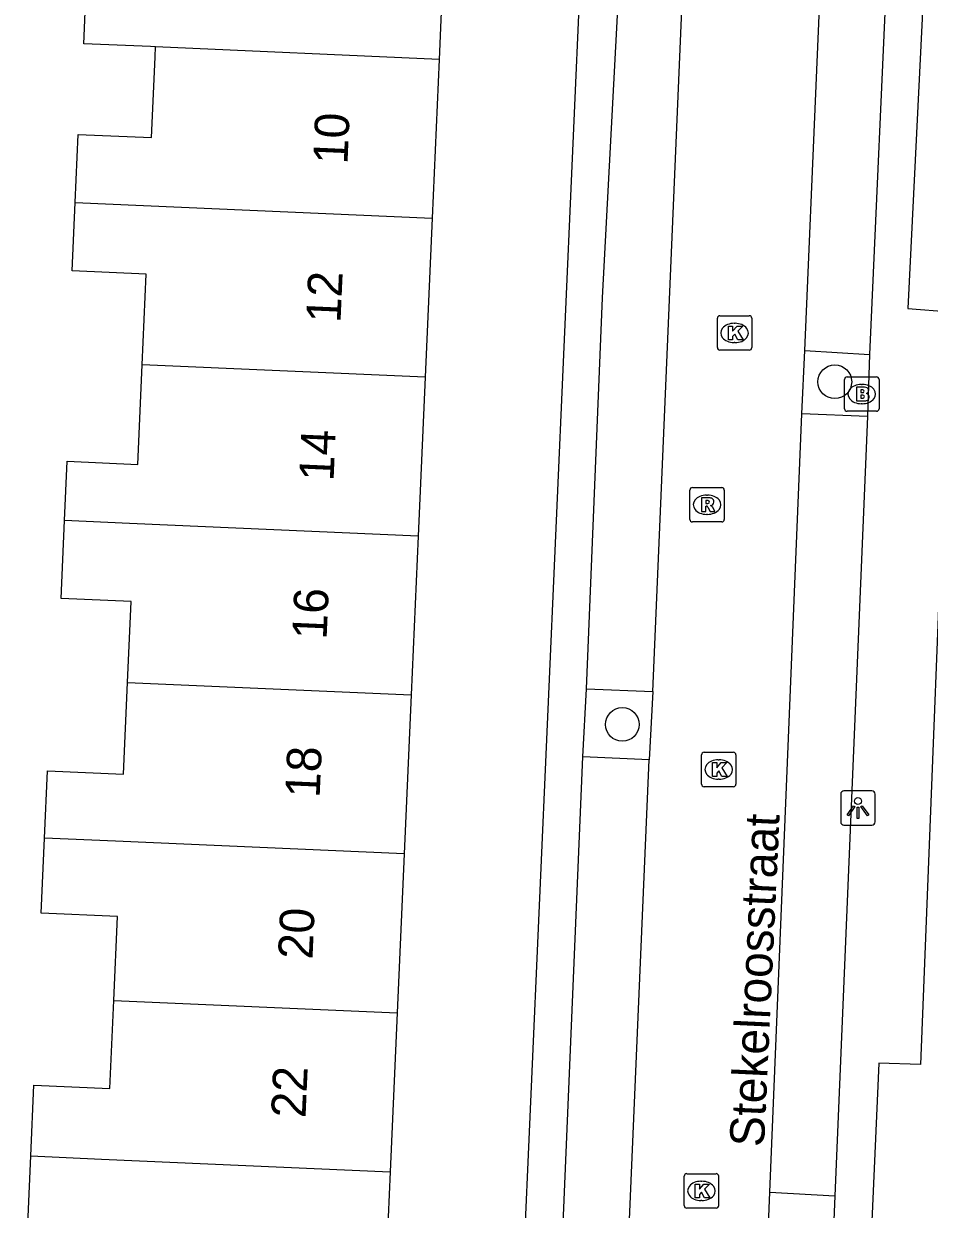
# Model space of a CAD drawing. Extents: x 162250 to 162654, y 380744 to 381605.
# Drawn here: x 162324.04 to 162350.32, y 381047.28 to 381081.68 of the extents above; entities that cross this region are included whole.
import ezdxf

# ---------------------------------------------------------------- set-up
doc = ezdxf.new("R2010")
doc.units = 0
for name, color, linetype in [('IMGEO_Boom', 7, 'Continuous'), ('IMGEO_Brandkraan', 7, 'Continuous'), ('IMGEO_Kolk', 7, 'Continuous'), ('IMGEO_Lichtpunt', 7, 'Continuous'), ('IMGEO_Openbare_ruimte_label', 7, 'Continuous'), ('IMGEO_Pand', 7, 'Continuous'), ('IMGEO_Pand_nummerreeks', 7, 'Continuous'), ('IMGEO_Parkeervlak_open', 7, 'Continuous'), ('IMGEO_Rijbaan_lokaal_open', 7, 'Continuous'), ('IMGEO_Rioolput', 7, 'Continuous'), ('IMGEO_Voetpad_open', 7, 'Continuous')]:
    doc.layers.add(name, color=color, linetype=linetype)

msp = doc.modelspace()

# ---------------------------------------------------------------- linework, layer by layer
at = {"layer": 'IMGEO_Boom'}
for centre in [(162347.576, 381071.289), (162341.411, 381061.348)]:
    msp.add_circle(centre, 0.489, dxfattribs=at)
at = {"layer": 'IMGEO_Brandkraan'}
for p, q in [((162347.858, 381070.506), (162347.858, 381071.358)), ((162347.933, 381071.432), (162348.785, 381071.432)), ((162348.859, 381071.358), (162348.859, 381070.506)), ((162348.346, 381071.212), (162348.371, 381071.212)), ((162348.369, 381070.652), (162348.344, 381070.652)), ((162348.785, 381070.432), (162347.933, 381070.432))]:
    msp.add_line(p, q, dxfattribs=at)
for points in [[(162347.858, 381070.506), (162347.858, 381071.358)], [(162347.933, 381071.432), (162348.785, 381071.432)], [(162348.859, 381071.358), (162348.859, 381070.506)], [(162348.206, 381071.132), (162348.206, 381070.732), (162348.419, 381070.732)], [(162348.437, 381071.132), (162348.206, 381071.132)], [(162348.385, 381071.051), (162348.331, 381071.051), (162348.331, 381070.975)], [(162348.331, 381070.975), (162348.384, 381070.975)], [(162348.393, 381070.899), (162348.331, 381070.899), (162348.331, 381070.818)], [(162348.331, 381070.818), (162348.393, 381070.818)], [(162348.785, 381070.432), (162347.933, 381070.432)]]:
    msp.add_lwpolyline(points, dxfattribs=at)
for centre, radius, start, end in [((162347.935, 381071.356), 0.0765, 91.552, 178.448), ((162347.935, 381071.356), 0.0765, 91.552, 178.448), ((162348.783, 381071.356), 0.0765, 1.552, 88.448), ((162348.783, 381071.356), 0.0765, 1.552, 88.448), ((162348.386, 381071.013), 0.0379, 267.8285, 90.9355), ((162348.441, 381070.987), 0.145, 59.4692, 91.5367), ((162348.466, 381071.034), 0.0922, 285.5137, 58.1501), ((162348.471, 381070.842), 0.105, 301.3115, 78.989), ((162348.394, 381070.858), 0.0404, 269.8759, 90.5077), ((162348.425, 381070.983), 0.251, 268.6676, 293.5347), ((162347.935, 381070.508), 0.0765, 181.552, 268.448), ((162347.935, 381070.508), 0.0765, 181.552, 268.448), ((162348.783, 381070.508), 0.0765, 271.552, 358.448), ((162348.783, 381070.508), 0.0765, 271.552, 358.448)]:
    msp.add_arc(centre, radius, start, end, dxfattribs=at)
for centre, major_axis, ratio, start_param, end_param in [((162348.345, 381070.932), (-0.387, 0.002), 0.722429, 4.712389, 7.853982), ((162348.37, 381070.932), (-0.39, 0.002), 0.717154, 1.570796, 4.712389)]:
    msp.add_ellipse(centre, major_axis=major_axis, ratio=ratio, start_param=start_param, end_param=end_param, dxfattribs=at)
at = {"layer": 'IMGEO_Kolk'}
for p, q in [((162344.168, 381072.279), (162344.168, 381073.131)), ((162344.243, 381073.205), (162345.095, 381073.205)), ((162345.169, 381073.131), (162345.169, 381072.279)), ((162344.656, 381072.985), (162344.681, 381072.985)), ((162344.679, 381072.425), (162344.654, 381072.425)), ((162345.095, 381072.205), (162344.243, 381072.205)), ((162343.707, 381059.615), (162343.707, 381060.467)), ((162343.782, 381060.541), (162344.634, 381060.541)), ((162344.195, 381060.321), (162344.22, 381060.321)), ((162344.708, 381060.467), (162344.708, 381059.615)), ((162344.218, 381059.761), (162344.193, 381059.761)), ((162344.634, 381059.541), (162343.782, 381059.541)), ((162343.205, 381047.389), (162343.205, 381048.241)), ((162343.28, 381048.315), (162344.132, 381048.315)), ((162344.206, 381048.241), (162344.206, 381047.389)), ((162343.693, 381048.095), (162343.718, 381048.095)), ((162344.132, 381047.315), (162343.28, 381047.315)), ((162343.716, 381047.535), (162343.691, 381047.535))]:
    msp.add_line(p, q, dxfattribs=at)
for points in [[(162344.168, 381072.279), (162344.168, 381073.131)], [(162344.243, 381073.205), (162345.095, 381073.205)], [(162345.169, 381073.131), (162345.169, 381072.279)], [(162344.489, 381072.905), (162344.612, 381072.905), (162344.612, 381072.754), (162344.742, 381072.905), (162344.906, 381072.905), (162344.76, 381072.754), (162344.913, 381072.505), (162344.761, 381072.505), (162344.676, 381072.669), (162344.612, 381072.602), (162344.612, 381072.505), (162344.489, 381072.505), (162344.489, 381072.905)], [(162345.095, 381072.205), (162344.243, 381072.205)], [(162343.707, 381059.615), (162343.707, 381060.467)], [(162343.782, 381060.541), (162344.634, 381060.541)], [(162344.708, 381060.467), (162344.708, 381059.615)], [(162344.028, 381060.241), (162344.151, 381060.241), (162344.151, 381060.09), (162344.281, 381060.241), (162344.445, 381060.241), (162344.299, 381060.09), (162344.452, 381059.841), (162344.3, 381059.841), (162344.215, 381060.005), (162344.151, 381059.938), (162344.151, 381059.841), (162344.028, 381059.841), (162344.028, 381060.241)], [(162344.634, 381059.541), (162343.782, 381059.541)], [(162343.205, 381047.389), (162343.205, 381048.241)], [(162343.28, 381048.315), (162344.132, 381048.315)], [(162344.206, 381048.241), (162344.206, 381047.389)], [(162343.526, 381048.015), (162343.649, 381048.015), (162343.649, 381047.864), (162343.779, 381048.015), (162343.943, 381048.015), (162343.797, 381047.864), (162343.95, 381047.615), (162343.798, 381047.615), (162343.713, 381047.779), (162343.649, 381047.712), (162343.649, 381047.615), (162343.526, 381047.615), (162343.526, 381048.015)], [(162344.132, 381047.315), (162343.28, 381047.315)]]:
    msp.add_lwpolyline(points, dxfattribs=at)
for centre, start, end in [((162344.245, 381073.129), 91.552, 178.448), ((162344.245, 381073.129), 91.552, 178.448), ((162345.093, 381073.129), 1.552, 88.448), ((162345.093, 381073.129), 1.552, 88.448), ((162344.245, 381072.281), 181.552, 268.448), ((162344.245, 381072.281), 181.552, 268.448), ((162345.093, 381072.281), 271.552, 358.448), ((162345.093, 381072.281), 271.552, 358.448), ((162343.784, 381060.465), 91.552, 178.448), ((162343.784, 381060.465), 91.552, 178.448), ((162344.632, 381060.465), 1.552, 88.448), ((162344.632, 381060.465), 1.552, 88.448), ((162343.784, 381059.617), 181.552, 268.448), ((162343.784, 381059.617), 181.552, 268.448), ((162344.632, 381059.617), 271.552, 358.448), ((162344.632, 381059.617), 271.552, 358.448), ((162343.282, 381048.239), 91.552, 178.448), ((162343.282, 381048.239), 91.552, 178.448), ((162344.13, 381048.239), 1.552, 88.448), ((162344.13, 381048.239), 1.552, 88.448), ((162343.282, 381047.391), 181.552, 268.448), ((162343.282, 381047.391), 181.552, 268.448), ((162344.13, 381047.391), 271.552, 358.448), ((162344.13, 381047.391), 271.552, 358.448)]:
    msp.add_arc(centre, 0.0765, start, end, dxfattribs=at)
for centre, major_axis, ratio, start_param, end_param in [((162344.655, 381072.705), (-0.387, 0.002), 0.722429, 4.712389, 7.853982), ((162344.68, 381072.705), (-0.39, 0.002), 0.717154, 1.570796, 4.712389), ((162344.194, 381060.041), (-0.387, 0.002), 0.722429, 4.712389, 7.853982), ((162344.219, 381060.041), (-0.39, 0.002), 0.717154, 1.570796, 4.712389), ((162343.692, 381047.815), (-0.387, 0.002), 0.722429, 4.712389, 7.853982), ((162343.717, 381047.815), (-0.39, 0.002), 0.717154, 1.570796, 4.712389)]:
    msp.add_ellipse(centre, major_axis=major_axis, ratio=ratio, start_param=start_param, end_param=end_param, dxfattribs=at)
at = {"layer": 'IMGEO_Lichtpunt'}
for p, q in [((162347.748, 381059.327), (162347.748, 381058.52)), ((162347.748, 381059.327), (162347.748, 381058.52)), ((162348.65, 381059.422), (162347.842, 381059.422)), ((162348.65, 381059.422), (162347.842, 381059.422)), ((162348.744, 381058.52), (162348.744, 381059.327)), ((162348.744, 381058.52), (162348.744, 381059.327)), ((162347.842, 381058.426), (162348.65, 381058.426)), ((162347.842, 381058.426), (162348.65, 381058.426))]:
    msp.add_line(p, q, dxfattribs=at)
for points in [[(162348.122, 381058.991), (162348.161, 381058.963), (162347.973, 381058.701), (162347.935, 381058.728), (162348.122, 381058.991)], [(162348.224, 381058.943), (162348.271, 381058.943), (162348.271, 381058.621), (162348.224, 381058.621), (162348.224, 381058.943)], [(162348.334, 381058.963), (162348.372, 381058.99), (162348.559, 381058.728), (162348.52, 381058.7), (162348.334, 381058.963)]]:
    msp.add_lwpolyline(points, dxfattribs=at)
msp.add_circle((162348.247, 381059.125), 0.0994, dxfattribs=at)
for centre, start, end in [((162347.842, 381059.327), 90, 180), ((162347.842, 381059.327), 90, 180), ((162348.65, 381059.327), 0, 90), ((162348.65, 381059.327), 0, 90), ((162347.842, 381058.52), 180, 270), ((162347.842, 381058.52), 180, 270), ((162348.65, 381058.52), 270, 0), ((162348.65, 381058.52), 270, 360)]:
    msp.add_arc(centre, 0.0946, start, end, dxfattribs=at)
at = {"layer": 'IMGEO_Pand'}
for points in [[(162327.869, 381081.005), (162327.721, 381081.011), (162325.787, 381081.096), (162325.868, 381082.941), (162328.005, 381082.846), (162328.125, 381085.575), (162330.088, 381085.526)], [(162336.297, 381085.253), (162336.29, 381085.1), (162336.246, 381084.098), (162336.094, 381080.643)], [(162325.534, 381076.488), (162325.621, 381078.467), (162327.753, 381078.374), (162327.828, 381080.068), (162327.856, 381080.717), (162327.869, 381081.005)], [(162336.094, 381080.643), (162327.869, 381081.005)], [(162336.094, 381080.643), (162335.891, 381076.033)], [(162327.483, 381071.784), (162327.599, 381074.413), (162325.447, 381074.508), (162325.534, 381076.488)], [(162325.534, 381076.488), (162327.518, 381076.401), (162335.891, 381076.033)], [(162335.891, 381076.033), (162335.688, 381071.423)], [(162325.225, 381067.264), (162325.301, 381068.982), (162327.356, 381068.891), (162327.483, 381071.784)], [(162335.688, 381071.423), (162327.483, 381071.784)], [(162335.688, 381071.423), (162335.485, 381066.813)], [(162327.054, 381062.565), (162327.158, 381064.916), (162325.126, 381065.006), (162325.225, 381067.264)], [(162335.485, 381066.813), (162327.112, 381067.181), (162325.225, 381067.264)], [(162335.485, 381066.813), (162335.282, 381062.202)], [(162324.645, 381058.052), (162324.731, 381060.002), (162326.937, 381059.905), (162327.054, 381062.565)], [(162327.054, 381062.565), (162335.282, 381062.202)], [(162335.282, 381062.202), (162335.079, 381057.592)], [(162326.654, 381053.343), (162326.761, 381055.776), (162324.549, 381055.873), (162324.645, 381058.052)], [(162335.079, 381057.592), (162326.706, 381057.961), (162324.645, 381058.052)], [(162335.079, 381057.592), (162334.877, 381052.982)], [(162324.247, 381048.83), (162324.337, 381050.884), (162326.542, 381050.787), (162326.654, 381053.343)], [(162326.654, 381053.343), (162334.877, 381052.982)], [(162334.877, 381052.982), (162334.674, 381048.372)], [(162326.278, 381044.122), (162324.044, 381044.22), (162324.153, 381046.694), (162324.169, 381047.067), (162324.247, 381048.83)], [(162324.247, 381048.83), (162326.3, 381048.74), (162334.674, 381048.372)], [(162334.674, 381048.372), (162334.471, 381043.762)]]:
    msp.add_lwpolyline(points, dxfattribs=at)
at = {"layer": 'IMGEO_Parkeervlak_open'}
for points in [[(162346.706, 381072.194), (162348.578, 381072.082)], [(162348.521, 381070.283), (162346.618, 381070.36)], [(162340.374, 381062.382), (162342.292, 381062.308)], [(162342.186, 381060.322), (162340.262, 381060.408)], [(162345.691, 381047.775), (162347.574, 381047.676)]]:
    msp.add_lwpolyline(points, dxfattribs=at)
at = {"layer": 'IMGEO_Rijbaan_lokaal_open'}
for points in [[(162346.706, 381072.194), (162347.384, 381088.031)], [(162342.292, 381062.308), (162343.253, 381084.815)], [(162346.618, 381070.36), (162346.706, 381072.194)], [(162345.691, 381047.775), (162346.618, 381070.36)], [(162342.292, 381062.308), (162342.186, 381060.322)], [(162341.453, 381043.139), (162342.186, 381060.322)], [(162345.617, 381045.871), (162345.691, 381047.775)]]:
    msp.add_lwpolyline(points, dxfattribs=at)
at = {"layer": 'IMGEO_Rioolput'}
for p, q in [((162343.444, 381068.222), (162344.296, 381068.222)), ((162343.369, 381067.296), (162343.369, 381068.148)), ((162343.857, 381068.002), (162343.882, 381068.002)), ((162344.37, 381068.148), (162344.37, 381067.296)), ((162344.296, 381067.222), (162343.444, 381067.222)), ((162343.88, 381067.442), (162343.855, 381067.442))]:
    msp.add_line(p, q, dxfattribs=at)
for points in [[(162343.444, 381068.222), (162344.296, 381068.222)], [(162343.369, 381067.296), (162343.369, 381068.148)], [(162343.958, 381067.92), (162343.706, 381067.922), (162343.706, 381067.522)], [(162344.37, 381068.148), (162344.37, 381067.296)], [(162343.706, 381067.522), (162343.83, 381067.522), (162343.83, 381067.684), (162343.841, 381067.684)], [(162343.884, 381067.841), (162343.83, 381067.841), (162343.83, 381067.76)], [(162343.83, 381067.76), (162343.882, 381067.76)], [(162343.888, 381067.655), (162343.959, 381067.522), (162344.099, 381067.522), (162344.034, 381067.648)], [(162344.296, 381067.222), (162343.444, 381067.222)]]:
    msp.add_lwpolyline(points, dxfattribs=at)
for centre, radius, start, end in [((162343.446, 381068.146), 0.0765, 91.552, 178.448), ((162343.446, 381068.146), 0.0765, 91.552, 178.448), ((162344.294, 381068.146), 0.0765, 1.552, 88.448), ((162344.294, 381068.146), 0.0765, 1.552, 88.448), ((162343.957, 381067.81), 0.109, 350.3612, 89.416), ((162343.84, 381067.631), 0.0533, 26.0293, 88.6989), ((162343.866, 381067.949), 0.19, 274.7715, 282.9687), ((162343.89, 381067.745), 0.0964, 77.0061, 93.1865), ((162343.904, 381067.802), 0.0378, 276.6634, 79.6772), ((162343.955, 381067.81), 0.112, 277.5842, 350.9817), ((162343.939, 381067.595), 0.108, 29.5134, 73.7905), ((162343.446, 381067.298), 0.0765, 181.552, 268.448), ((162343.446, 381067.298), 0.0765, 181.552, 268.448), ((162344.294, 381067.298), 0.0765, 271.552, 358.448), ((162344.294, 381067.298), 0.0765, 271.552, 358.448)]:
    msp.add_arc(centre, radius, start, end, dxfattribs=at)
for centre, major_axis, ratio, start_param, end_param in [((162343.856, 381067.722), (-0.387, 0.002), 0.722429, 4.712389, 7.853982), ((162343.881, 381067.722), (-0.39, 0.002), 0.717154, 1.570796, 4.712389)]:
    msp.add_ellipse(centre, major_axis=major_axis, ratio=ratio, start_param=start_param, end_param=end_param, dxfattribs=at)
at = {"layer": 'IMGEO_Voetpad_open'}
for points in [[(162349.681, 381096.654), (162348.578, 381072.082)], [(162336.141, 380988.151), (162336.6, 381000), (162337.62, 381024.184), (162335.584, 381024.354), (162336.016, 381034.263), (162338.044, 381034.203), (162340.701, 381094.418)], [(162350.659, 381092.985), (162349.693, 381073.414), (162350.924, 381073.314), (162350.066, 381051.483), (162348.851, 381051.523), (162346.572, 381000), (162346.066, 380986.918)], [(162340.374, 381062.382), (162340.838, 381073.728), (162341.423, 381084.846)], [(162348.578, 381072.082), (162348.521, 381070.283)], [(162348.521, 381070.283), (162347.574, 381047.676)], [(162340.262, 381060.408), (162340.374, 381062.382)], [(162339.268, 381036.765), (162340.262, 381060.408)], [(162347.574, 381047.676), (162347.499, 381045.78)]]:
    msp.add_lwpolyline(points, dxfattribs=at)

# ---------------------------------------------------------------- texts
at = {"layer": 'IMGEO_Openbare_ruimte_label'}
msp.add_text('Stekelroosstraat', height=1, rotation=87.3064, dxfattribs=at).set_placement((162345.52, 381049.077))
at = {"layer": 'IMGEO_Pand_nummerreeks'}
for s, rotation, p in [('10', 87.4792, (162333.436, 381077.586)), ('12', 87.4803, (162333.234, 381072.986)), ('14', 87.4803, (162333.032, 381068.394)), ('16', 87.4803, (162332.83, 381063.799)), ('18', 87.4803, (162332.628, 381059.206)), ('20', 87.4803, (162332.421, 381054.52)), ('22', 87.4803, (162332.219, 381049.919))]:
    msp.add_text(s, height=1, rotation=rotation, dxfattribs=at).set_placement(p)

doc.saveas('drawing.dxf')
